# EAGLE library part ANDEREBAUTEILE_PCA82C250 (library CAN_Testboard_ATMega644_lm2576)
PCA82C250 CAN Bustreiber
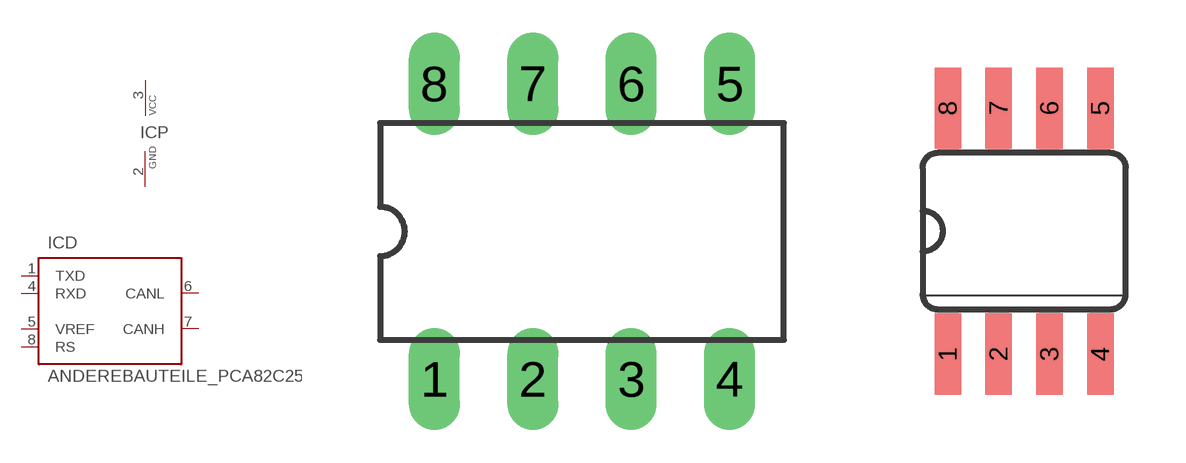
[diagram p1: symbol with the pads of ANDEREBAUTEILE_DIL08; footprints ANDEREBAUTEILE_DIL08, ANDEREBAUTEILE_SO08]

Designator prefix IC; gates D=ANDEREBAUTEILE_82C250 P=ANDEREBAUTEILE_VCC-GND

## ANDEREBAUTEILE_PCA82C250  [ANDEREBAUTEILE_DIL08]
1  D:TXD
2  P:GND  pwr
3  P:VCC  pwr
4  D:RXD
5  D:VREF
6  D:CANL
7  D:CANH
8  D:RS

## ANDEREBAUTEILE_PCA82C250T  [ANDEREBAUTEILE_SO08]
Pads as for ANDEREBAUTEILE_DIL08

## Footprint ANDEREBAUTEILE_DIL08 (pad centres in mm)
drill 0.813 long: 1 -3.81,-3.81; 2 -1.27,-3.81; 3 1.27,-3.81; 4 3.81,-3.81; 5 3.81,3.81; 6 1.27,3.81; 7 -1.27,3.81; 8 -3.81,3.81

## Footprint ANDEREBAUTEILE_SO08 (pad centres in mm)
smd 0.66 x 2.032: 1 -1.905,-3.073; 2 -0.635,-3.073; 3 0.635,-3.073; 4 1.905,-3.073; 5 1.905,3.073; 6 0.635,3.073; 7 -0.635,3.073; 8 -1.905,3.073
